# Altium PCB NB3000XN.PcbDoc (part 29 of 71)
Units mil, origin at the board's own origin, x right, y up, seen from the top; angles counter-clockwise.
Board outline 9527.56 x 6929.77 mil, 6 copper layers (Top Layer, GND+SHIELD, MidLayer1, MidLayer2, P2 - 3V3+5V0, Bottom Layer), stack 62.375 mil thick; 832 components, 1027 nets, 4655 pads, 4981 vias.
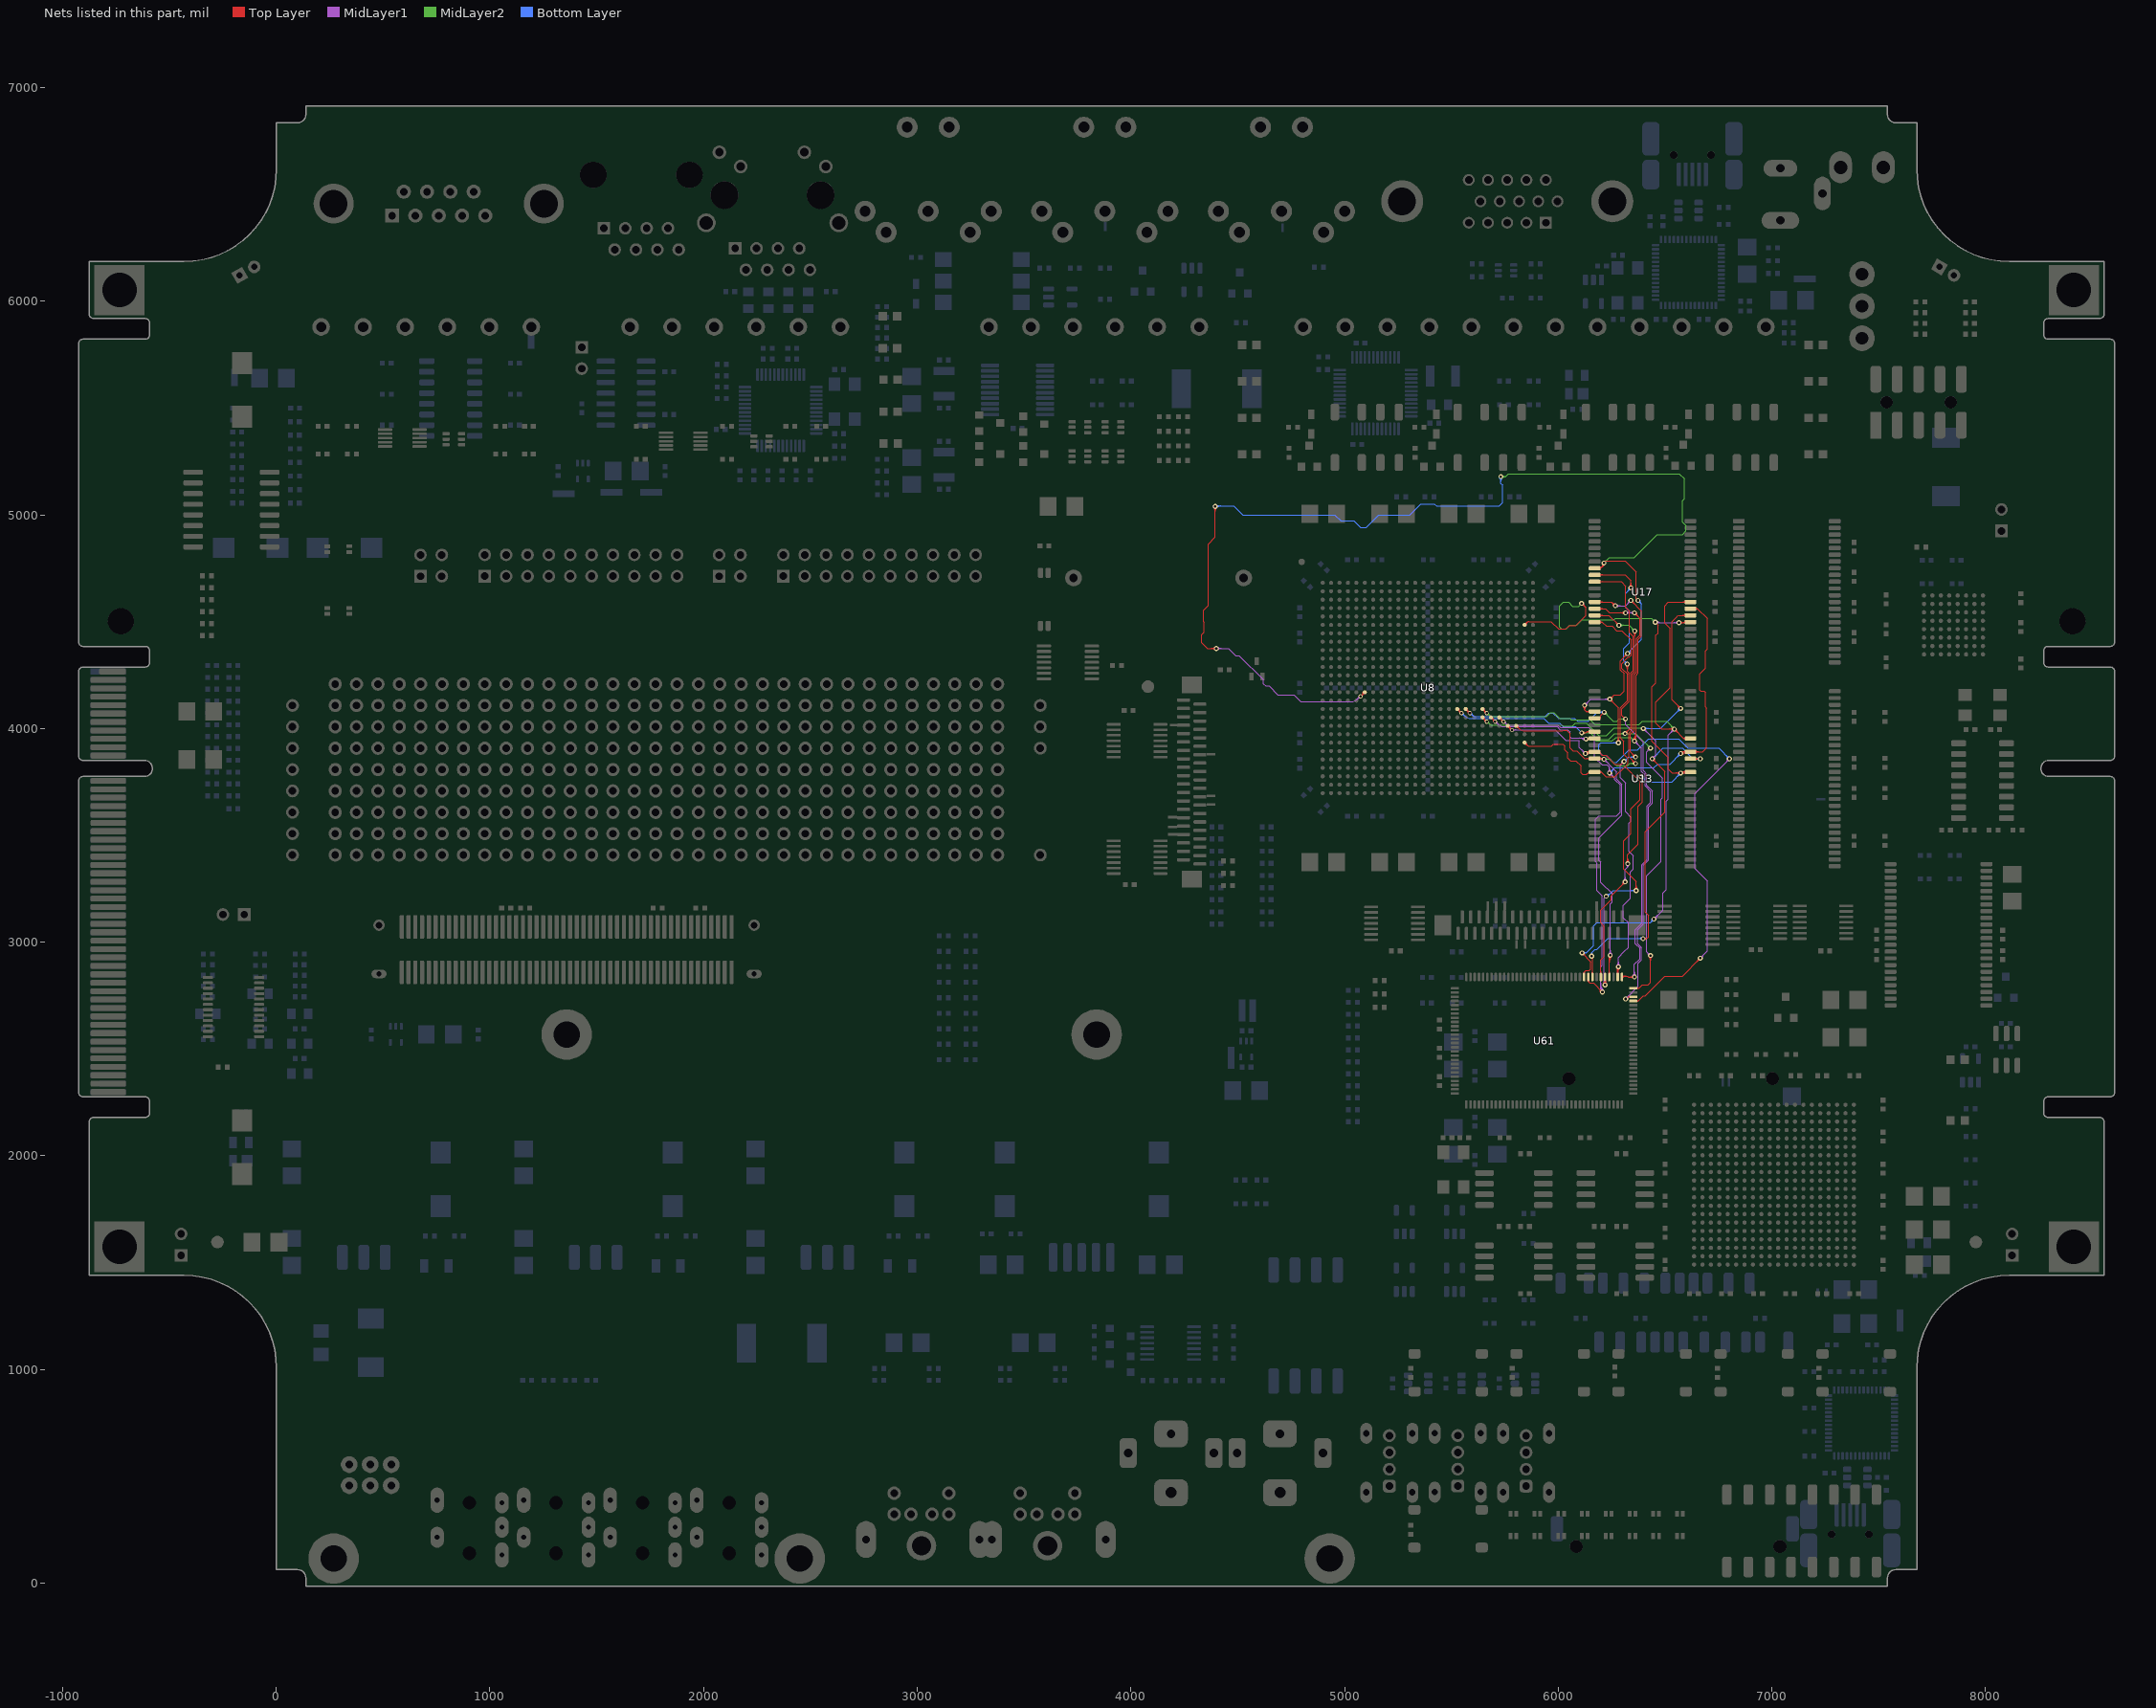
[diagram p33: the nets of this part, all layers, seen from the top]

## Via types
v1: diameter 23, hole 11.81, Top Layer to Bottom Layer, 3672 vias
v2: diameter 26, hole 11.81, Top Layer to Bottom Layer, 461 vias
v3: diameter 19, hole 11.81, Top Layer to Bottom Layer, tented both sides, 396 vias
v4: diameter 23.62, hole 11.81, Top Layer to Bottom Layer, 288 vias
v5: diameter 20, hole 11.81, Top Layer to Bottom Layer, 91 vias
v6: diameter 23, hole 11.81, Top Layer to Bottom Layer, tented both sides, 50 vias
v7: diameter 31, hole 11.81, Top Layer to Bottom Layer, 15 vias
v8: diameter 27.56, hole 11.81, Top Layer to Bottom Layer, tented both sides, 4 vias
v9: diameter 29, hole 11.81, Top Layer to Bottom Layer, 3 vias
v10: diameter 21, hole 11.81, Top Layer to Bottom Layer, 1 vias

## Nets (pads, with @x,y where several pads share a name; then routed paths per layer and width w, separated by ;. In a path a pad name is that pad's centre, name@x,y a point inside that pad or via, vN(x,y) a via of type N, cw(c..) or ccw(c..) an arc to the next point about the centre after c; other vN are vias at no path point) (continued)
DB_MEM.BUS_D17: U8.P6 U13.4 U17.8 U61.61 | length 9838.7
  Top Layer w4: v1@4388.28,5033.28 cw(c4372.06,5017.06) 4395,5017.06 cw(c4417.93,5017.06) v1@4401.72,5033.28 ; v1@4391.11,5036.11 cw(c4381.72,5026.72) 4395,5026.72 cw(c4408.28,5026.72) v1@4398.89,5036.11 ; v4@4393.06,4368.1 ccw(c4376.31,4351.35) 4376.31,4375.04 ccw(c4376.31,4398.73) v4@4393.06,4381.98 ; v1(4395,5040) 4395,4896.1 4362.02,4863.13 4362.02,4577.02 4340,4555 4340,4500.59 4343,4497.59 4343,4451.2 4332.02,4440.23 4332.02,4401.13 4358.11,4375.04 v4(4400,4375.04) ; v4@4395.89,4370.93 ccw(c4385.97,4361.01) 4385.97,4375.04 ccw(c4385.97,4389.07) v4@4395.89,4379.15 ; v3(5075.04,4150.63) U8.P6@5094.72,4170.31 ; U8.P6@5087.22,4170.31 cw(c5069.12,4170.31) 5081.92,4157.51 cw(c5094.72,4144.71) U8.P6@5094.72,4162.81 ; U8.P6@5087.38,4170.31 cw(c5069.66,4170.31) 5082.19,4157.78 cw(c5094.72,4145.25) U8.P6@5094.72,4162.97 ; v1@6117.62,4101.27 cw(c6107.92,4089.04) 6123.52,4089.04 ; v1(6123.52,4108.71) 6123.52,4089.04 ; v1@6129.43,4101.27 ccw(c6139.13,4089.04) 6123.52,4089.04 ; U13.4@6147.37,4074.3 ccw(c6133.72,4060.65) 6133.72,4079.96 ccw(c6133.72,4099.27) U13.4@6147.37,4085.62 ; U13.4@6170.59,4079.96 6132.6,4079.96 6123.52,4089.04 ; U17.8@6170.59,4750.24 6199.72,4750.24 ; U17.8@6187.19,4746.35 ccw(c6190.23,4758.62) 6199.17,4749.68 ; U17.8@6188.15,4750.24 ccw(c6192.22,4766.65) 6204.17,4754.69 ; U17.8@6189.11,4754.12 ccw(c6194.21,4774.67) 6209.18,4759.7 ; U17.8@6190.07,4758 ccw(c6196.2,4782.7) v1@6214.19,4764.71 ; U17.8@6195.63,4747.41 cw(c6199.72,4745.87) 6199.72,4750.24 ; U17.8@6195.63,4753.06 ccw(c6199.72,4754.6) 6199.72,4750.24 ; 6204.89,4755.4 ccw(c6196.85,4763.44) v1@6206.29,4769.76 ; 6208.33,4758.85 ccw(c6200.98,4766.2) v1@6209.62,4771.98 ; 6211.77,4762.29 ccw(c6205.1,4768.96) v1@6212.94,4774.21 ; v1@6241.52,4128.21 cw(c6241.52,4105.27) 6257.74,4121.49 cw(c6273.96,4137.71) 6251.02,4137.71 cw(c6273.96,4137.71) 6257.74,4153.93 cw(c6241.52,4170.14) v1@6241.52,4147.21 ; v1@6241.52,4132.21 cw(c6241.52,4118.93) 6250.91,4128.32 cw(c6260.3,4137.71) 6247.02,4137.71 cw(c6260.3,4137.71) 6250.91,4147.1 cw(c6241.52,4156.49) v1@6241.52,4143.21 ; v1@6275.14,3940.09 ccw(c6258.92,3956.31) 6281.86,3956.31 ccw(c6304.79,3956.31) v1@6288.57,3940.09 ; v1@6277.97,3937.26 ccw(c6268.58,3946.65) 6281.86,3946.65 ccw(c6295.14,3946.65) v1@6285.75,3937.26 ; v1(6281.86,3933.37) 6281.86,4097.37 v1(6241.52,4137.71) 6262.19,4158.37 6290.19,4158.37 6307.86,4176.04 6307.86,4257.37 6290.19,4275.04 6290.19,4316.71 v1(6324.86,4351.37) ; v1@6315.36,4351.37 cw(c6292.42,4351.37) 6308.64,4335.16 cw(c6324.86,4318.94) v1@6324.86,4341.87 ; v1@6319.36,4351.37 cw(c6306.08,4351.37) 6315.47,4341.99 cw(c6324.86,4332.6) v1@6324.86,4345.87 ; U61.61@6351.93,2725.05 6373.53,2725.05 ; U61.61@6368.23,2722.52 cw(c6373.53,2718.22) 6373.53,2725.05 ; U61.61@6368.23,2727.57 ccw(c6373.53,2731.87) 6373.53,2725.05 ; v1(6373.52,4600.04) 6365.19,4608.37 6365.19,4733.71 6313.52,4785.37 6224.52,4785.37 v1(6214.19,4775.04) v1@6214.19,4764.71 ; v1@6655.69,2925.04 cw(c6632.76,2925.04) 6648.97,2908.82 cw(c6665.19,2892.61) v1@6665.19,2915.54 ; v1@6659.69,2925.04 cw(c6646.41,2925.04) 6655.8,2915.65 cw(c6665.19,2906.26) v1@6665.19,2919.54 ; v1(6665.19,2925.04) 6581.86,2841.71 6498.52,2841.71 6406.86,2750.04 6398.52,2750.04 6373.53,2725.05 ; 5087.84,4163.43 cw(c5075.04,4176.24) 5075.04,4158.13 ccw(c5075.04,4176.24) 5087.84,4163.43 ; 5087.84,4163.43 ccw(c5100.65,4150.63) 5082.54,4150.63 cw(c5100.65,4150.63) 5087.84,4163.43 ; 6199.72,4750.24 v1@6214.19,4764.71
  MidLayer1 w4: v4(4400,4375.04) 4456.86,4375.04 4490.19,4341.71 4506.86,4341.71 4620.07,4228.5 4620.07,4209.4 4630.5,4198.97 4646.87,4198.97 4688.29,4157.54 4730,4157.54 4764.33,4157.54 4773.52,4148.35 4795.11,4126.77 4855.26,4126.77 4860,4126.77 4870,4126.77 4918.62,4126.77 4938.04,4126.77 5012.16,4126.77 ; v4@4404.11,4370.93 cw(c4414.03,4361.01) 4414.03,4375.04 cw(c4414.03,4389.07) v4@4404.11,4379.15 ; v4@4406.94,4368.1 cw(c4423.69,4351.35) 4423.69,4375.04 cw(c4423.69,4398.73) v4@4406.94,4381.98 ; 4998.23,4126.77 5012.16,4126.77 ; v3@5067.57,4151.28 cw(c5049.53,4152.86) 5061.17,4138.99 ; v3@5074.39,4143.16 ccw(c5072.81,4125.12) 5061.17,4138.99 ; v1(6123.52,4108.71) 6152.52,4137.71 v1(6241.52,4137.71) ; v1@6123.52,4114.21 ccw(c6123.52,4127.49) 6132.91,4118.1 ccw(c6142.3,4108.71) v1@6129.02,4108.71 ; v1@6123.52,4118.21 ccw(c6123.52,4141.14) 6139.74,4124.93 ccw(c6155.96,4108.71) v1@6133.02,4108.71 ; v1@6234.81,4130.99 ccw(c6218.59,4114.77) 6218.59,4137.71 ccw(c6218.59,4160.64) v1@6234.81,4144.43 ; v1@6237.64,4133.82 ccw(c6228.25,4124.43) 6228.25,4137.71 ccw(c6228.25,4150.99) v1@6237.64,4141.6 ; v1(6665.19,2925.04) 6698.52,2958.37 6698.52,3286.35 6640.19,3344.69 6640.19,3696.71 v1(6801.86,3858.37) ; v1@6665.19,2930.54 ccw(c6665.19,2943.82) 6674.58,2934.43 ccw(c6683.97,2925.04) v1@6670.69,2925.04 ; v1@6665.19,2934.54 ccw(c6665.19,2957.48) 6681.41,2941.26 ccw(c6697.63,2925.04) v1@6674.69,2925.04 ; v1@6792.36,3858.37 cw(c6769.42,3858.37) 6785.64,3842.16 cw(c6801.86,3825.94) v1@6801.86,3848.87 ; v1@6796.36,3858.37 cw(c6783.08,3858.37) 6792.47,3848.99 cw(c6801.86,3839.6) v1@6801.86,3852.87 ; 5012.16,4126.77 5031.66,4126.77 ccw(c5031.66,4168.5) 5061.17,4138.99
  MidLayer2 w4: v1(5731.86,5179.04) 5753.21,5179.04 ; v1@5735.94,5175.36 cw(c5744.22,5167.9) 5744.22,5179.04 cw(c5744.22,5190.18) v1@5735.94,5182.72 ; v1@5738.91,5172.68 cw(c5753.21,5159.8) 5753.21,5179.04 ; v1@5738.91,5185.4 ccw(c5753.21,5198.28) 5753.21,5179.04 ; v1(6214.19,4775.04) 6239.19,4800.04 6356.21,4800.04 6464.54,4908.37 6581.86,4908.37 6598.52,4925.04 6598.52,4950.04 6581.86,4966.71 6581.86,5066.71 6590.19,5075.04 6590.19,5169.08 6567.56,5191.71 5765.88,5191.71 5753.21,5179.04 ; v1@6214.19,4780.54 ccw(c6214.19,4793.82) 6223.58,4784.43 ccw(c6232.97,4775.04) v1@6219.69,4775.04 ; v1@6214.19,4784.54 ccw(c6214.19,4807.48) 6230.41,4791.26 ccw(c6246.63,4775.04) v1@6223.69,4775.04
  Bottom Layer w4: v1(4395,5040) 4385.62,5040 4385.62,5041.71 4481.86,5041.71 4523.52,5000.04 4954.51,5000.04 4954.77,4999.77 ; v1@4398.89,5036.11 cw(c4412.4,5022.6) 4412.4,5041.71 ; v1@4401.72,5033.28 cw(c4422.06,5012.94) 4422.06,5041.71 ; v1@4401.72,5046.72 ccw(c4413.81,5058.81) 4413.81,5041.71 ; 4955,5000 4982.46,4972.54 5044.28,4972.54 5075.94,4940.87 5101.02,4940.87 5160.15,5000 5305.48,5000 5330.52,5025.04 5356.86,5051.37 5420.33,5051.37 5430,5041.71 5723.52,5041.71 5740.19,5058.37 5740.19,5140 5731.86,5148.33 v1(5731.86,5179.04) ; v1@5725.14,5172.32 cw(c5708.92,5156.11) 5731.86,5156.11 cw(c5754.79,5156.11) v1@5738.57,5172.32 ; v1@5727.97,5175.15 cw(c5718.58,5165.76) 5731.86,5165.76 cw(c5745.14,5165.76) v1@5735.75,5175.15 ; v1@6275.14,3926.66 ccw(c6258.92,3910.44) 6258.92,3933.37 ccw(c6258.92,3956.31) v1@6275.14,3940.09 ; v1@6277.97,3929.49 ccw(c6268.58,3920.1) 6268.58,3933.37 ccw(c6268.58,3946.65) v1@6277.97,3937.26 ; v1(6281.86,3933.37) 6198.52,3933.37 6190.19,3925.04 6190.19,3891.71 6206.86,3875.04 6223.52,3875.04 6257.02,3841.54 6272.44,3841.54 6330.27,3899.37 6371.48,3899.37 6422.82,3950.71 6564.52,3950.71 6606.86,3908.37 6751.86,3908.37 v1(6801.86,3858.37) ; v1(6324.86,4351.37) 6390.19,4416.71 6390.19,4583.37 v1(6373.52,4600.04) ; v1@6324.86,4356.87 ccw(c6324.86,4370.15) 6334.25,4360.76 ccw(c6343.64,4351.37) v1@6330.36,4351.37 ; v1@6324.86,4360.87 ccw(c6324.86,4383.81) 6341.07,4367.59 ccw(c6357.29,4351.37) v1@6334.36,4351.37 ; v1@6373.52,4590.54 cw(c6373.52,4567.61) 6389.74,4583.82 cw(c6405.96,4600.04) v1@6383.02,4600.04 ; v1@6373.52,4594.54 cw(c6373.52,4581.26) 6382.91,4590.65 cw(c6392.3,4600.04) v1@6379.02,4600.04 ; v1@6792.36,3858.37 ccw(c6769.42,3858.37) 6785.64,3874.59 ccw(c6801.86,3890.81) v1@6801.86,3867.87 ; v1@6796.36,3858.37 ccw(c6783.08,3858.37) 6792.47,3867.76 ccw(c6801.86,3877.15) v1@6801.86,3863.87
DB_MEM.BUS_D18: U8.T18 U13.5 U17.9 U61.62 | length 3809.3
  Top Layer w4: U8.T18@5567.17,4084.07 cw(c5567.17,4065.97) 5579.97,4078.77 cw(c5592.77,4091.57) U8.T18@5574.67,4091.57 ; U8.T18@5567.17,4084.23 cw(c5567.17,4066.51) 5579.7,4079.04 cw(c5592.23,4091.57) U8.T18@5574.51,4091.57 ; U8.T18@5567.17,4091.57 v3(5586.85,4071.89) ; U13.5@6170.59,4048.46 6198.15,4048.46 6200.15,4050.46 6200.15,4061.33 v1(6215.19,4076.37) ; U17.9@6170.59,4718.74 6313.16,4718.74 6340.19,4691.71 v1(6340.19,4658.37) ; U17.9@6193.81,4713.08 cw(c6207.46,4699.43) 6207.46,4718.74 cw(c6207.46,4738.05) U17.9@6193.81,4724.4 ; v1(6315,4045) 6298.19,4061.81 6298.19,4093.06 6331.86,4126.73 6331.86,4260 6323.52,4268.33 v1(6323.52,4301.71) ; v1(6315.52,2734.37) 6319.64,2734.37 6330,2744.73 ; v1@6316.81,4294.99 cw(c6300.59,4278.77) 6323.52,4278.77 cw(c6346.46,4278.77) v1@6330.24,4294.99 ; v1@6319.64,4297.82 cw(c6310.25,4288.43) 6323.52,4288.43 cw(c6336.8,4288.43) v1@6327.41,4297.82 ; v1@6333.47,4665.09 ccw(c6317.26,4681.31) 6340.19,4681.31 ccw(c6363.13,4681.31) v1@6346.91,4665.09 ; U61.62@6335.71,2742.12 ccw(c6330,2737.18) 6330,2744.73 ; U61.62@6335.71,2747.35 cw(c6330,2752.28) 6330,2744.73 ; v1@6336.3,4662.26 ccw(c6326.91,4671.65) 6340.19,4671.65 ccw(c6353.47,4671.65) v1@6344.08,4662.26 ; U61.62@6351.93,2744.73 6330,2744.73 ; 5574.05,4084.69 cw(c5561.24,4071.89) 5579.35,4071.89 ccw(c5561.24,4071.89) 5574.05,4084.69 ; 5574.05,4084.69 ccw(c5586.85,4097.5) 5586.85,4079.39 cw(c5586.85,4097.5) 5574.05,4084.69
  MidLayer1 w4: v1@6315.19,4044.81 6315.19,4018.04 6398.52,3934.71 6398.52,3803.04 6415.19,3786.37 6415.19,3734.04 6440.86,3708.37 6440.86,3651.37 6423.52,3634.04 6423.52,3384.37 6398.86,3359.71 6398.86,3085.06 6371.19,3057.39 6371.19,2994.04 6390.19,2975.04 6390.19,2916.71 6374.86,2901.37 6374.86,2793.71 v1(6315.52,2734.37) ; v1@6315.52,2739.87 ccw(c6315.52,2753.15) 6324.91,2743.76 ccw(c6334.3,2734.37) v1@6321.02,2734.37 ; v1@6315.52,2743.87 ccw(c6315.52,2766.81) 6331.74,2750.59 ccw(c6347.96,2734.37) v1@6325.02,2734.37
  MidLayer2 w4: v1@6215.19,4066.87 cw(c6215.19,4043.94) 6231.41,4060.16 cw(c6247.63,4076.37) v1@6224.69,4076.37 ; v1@6215.19,4070.87 cw(c6215.19,4057.6) 6224.58,4066.99 cw(c6233.97,4076.37) v1@6220.69,4076.37 ; v1(6215.19,4076.37) 6256.56,4035 6275,4035 6284.81,4044.81 v1@6315.19,4044.81
  Bottom Layer w4: v3@5587.5,4064.42 cw(c5589.08,4046.38) 5600.72,4060.25 cw(c5612.36,4074.12) v3@5594.32,4072.54 ; 5600.43,4060.5 ccw(c5610.36,4070.43) 5610.36,4056.38 5703.9,4056.38 5910,4056.38 5920,4056.38 5924.74,4056.38 5938.41,4056.38 5954.52,4072.5 5976.19,4072.5 5997.19,4051.5 5997.19,4051.37 5999.86,4048.71 6076.88,4048.71 6092.21,4033.37 6140.19,4033.37 6183.19,4076.37 v1(6215.19,4076.37) ; v1@6208.47,4069.66 ccw(c6192.26,4053.44) 6192.26,4076.37 ccw(c6192.26,4099.31) v1@6208.47,4083.09 ; v1@6211.3,4072.49 ccw(c6201.91,4063.1) 6201.91,4076.37 ccw(c6201.91,4089.65) v1@6211.3,4080.26 ; v1@6314.02,4301.71 ccw(c6291.09,4301.71) 6307.31,4317.93 ccw(c6323.52,4334.14) v1@6323.52,4311.21 ; v1@6318.02,4301.71 ccw(c6304.75,4301.71) 6314.14,4311.1 ccw(c6323.52,4320.49) v1@6323.52,4307.21 ; v1(6323.52,4301.71) 6306.86,4318.37 6306.86,4374.71 6332.86,4400.71 6332.86,4549.04 6315.19,4566.71 6315.19,4633.37 v1(6340.19,4658.37) ; v1@6330.69,4658.37 cw(c6307.76,4658.37) 6323.97,4642.16 cw(c6340.19,4625.94) v1@6340.19,4648.87 ; v1@6334.69,4658.37 cw(c6321.41,4658.37) 6330.8,4648.99 cw(c6340.19,4639.6) v1@6340.19,4652.87
DB_MEM.BUS_D19: U8.T17 U13.7 U17.10 U61.64 | length 3878.3
  Top Layer w4: U8.T17@5527.8,4084.07 cw(c5527.8,4065.97) 5540.6,4078.77 cw(c5553.4,4091.57) U8.T17@5535.3,4091.57 ; U8.T17@5527.8,4084.23 cw(c5527.8,4066.51) 5540.33,4079.04 cw(c5552.86,4091.57) U8.T17@5535.14,4091.57 ; U8.T17@5527.8,4091.57 v3(5547.48,4071.89) ; v1(6110,3980) 6129.53,3980 ; v1@6117.47,3974.14 cw(c6129.53,3964.68) 6129.53,3980 ; v1@6117.47,3985.86 ccw(c6129.53,3995.32) 6129.53,3980 ; U13.7@6147.1,3980.1 ccw(c6135,3969.15) 6135,3985.47 ; U13.7@6147.1,3990.84 cw(c6135,4001.79) 6135,3985.47 ; U13.7@6170.59,3985.47 6135,3985.47 ; U17.10@6170.59,4687.24 6294.66,4687.24 6315.19,4666.71 6315.19,4566.71 6332.86,4549.04 6332.86,4449.04 6350.52,4431.37 6350.52,4270.65 6339.86,4259.98 6339.86,4003.71 v1(6312.86,3976.71) ; U17.10@6193.81,4681.59 cw(c6207.46,4667.93) 6207.46,4687.24 cw(c6207.46,4706.56) U17.10@6193.81,4692.9 ; v1@6312.86,3982.21 ccw(c6312.86,3995.49) 6322.25,3986.1 ccw(c6331.64,3976.71) v1@6318.36,3976.71 ; v1@6312.86,3986.21 ccw(c6312.86,4009.14) 6329.07,3992.93 ccw(c6345.29,3976.71) v1@6322.36,3976.71 ; U61.64@6351.93,2784.1 6377.52,2784.1 6394.8,2801.37 6421.37,2801.37 6431.86,2811.86 v1(6431.86,2937.37) ; U61.64@6367.96,2781.27 cw(c6374.78,2774.44) 6374.78,2784.1 cw(c6374.78,2793.76) U61.64@6367.96,2786.93 ; v1@6425.14,2930.66 cw(c6408.92,2914.44) 6431.86,2914.44 cw(c6454.79,2914.44) v1@6438.57,2930.66 ; v1@6427.97,2933.49 cw(c6418.58,2924.1) 6431.86,2924.1 cw(c6445.14,2924.1) v1@6435.75,2933.49 ; 5534.68,4084.69 cw(c5521.87,4071.89) 5539.98,4071.89 ccw(c5521.87,4071.89) 5534.68,4084.69 ; 5534.68,4084.69 ccw(c5547.48,4097.5) 5547.48,4079.39 cw(c5547.48,4097.5) 5534.68,4084.69 ; 6129.53,3980 6135,3985.47
  MidLayer1 w4: v1@6422.36,2937.37 ccw(c6399.42,2937.37) 6415.64,2953.59 ccw(c6431.86,2969.81) v1@6431.86,2946.87 ; v1@6422.36,3908.37 cw(c6399.42,3908.37) 6415.64,3892.16 cw(c6431.86,3875.94) v1@6431.86,3898.87 ; v1@6426.36,2937.37 ccw(c6413.08,2937.37) 6422.47,2946.76 ccw(c6431.86,2956.15) v1@6431.86,2942.87 ; v1@6426.36,3908.37 cw(c6413.08,3908.37) 6422.47,3898.99 cw(c6431.86,3889.6) v1@6431.86,3902.87 ; v1(6431.86,2937.37) 6414.86,2954.37 6414.86,3311.36 6481.86,3378.36 6481.86,3669.69 6489.19,3677.02 6489.19,3767.71 6415.19,3841.71 6415.19,3891.71 v1(6431.86,3908.37)
  MidLayer2 w4: v1(6110,3980) 6150.56,3980 6180.52,3950.04 6237.19,3950.04 6263.86,3976.71 v1(6312.86,3976.71) 6363.52,3976.71 6385.4,3954.83 v1(6431.86,3908.37) ; v1@6113.89,3976.11 cw(c6123.28,3966.72) 6123.28,3980 cw(c6123.28,3993.28) v1@6113.89,3983.89 ; v1@6116.72,3973.28 cw(c6132.93,3957.06) 6132.93,3980 cw(c6132.93,4002.93) v1@6116.72,3986.72 ; v1@6306.14,3969.99 ccw(c6289.92,3953.77) 6289.92,3976.71 ccw(c6289.92,3999.64) v1@6306.14,3983.43 ; v1@6308.97,3972.82 ccw(c6299.58,3963.43) 6299.58,3976.71 ccw(c6299.58,3989.99) v1@6308.97,3980.6 ; v1@6316.75,3972.82 cw(c6326.14,3963.43) 6326.14,3976.71 cw(c6326.14,3989.99) v1@6316.75,3980.6 ; v1@6319.57,3969.99 cw(c6335.79,3953.77) 6335.79,3976.71 cw(c6335.79,3999.64) v1@6319.57,3983.43 ; v1@6422.36,3908.37 ccw(c6399.42,3908.37) 6415.64,3924.59 ccw(c6431.86,3940.81) v1@6431.86,3917.87 ; v1@6426.36,3908.37 ccw(c6413.08,3908.37) 6422.47,3917.76 ccw(c6431.86,3927.15) v1@6431.86,3913.87
  Bottom Layer w4: v3@5548.13,4064.42 cw(c5549.71,4046.38) 5561.35,4060.25 ; v3@5554.95,4072.54 ccw(c5572.99,4074.12) 5561.35,4060.25 ; v1(6110,3980) 6081.29,4008.71 6023.19,4008.71 6006.86,4025.04 5954.84,4025.04 5931.86,4048.03 5924.74,4048.03 5920,4048.03 5910,4048.03 5703.9,4048.03 5684.48,4048.03 5610.36,4048.03 5590.86,4048.03 cw(c5590.86,4089.76) 5561.35,4060.25
DB_MEM.BUS_D20: U8.U21 U13.8 U17.13 U61.65 | length 3875
  Top Layer w4: U8.U21@5685.28,4044.7 cw(c5685.28,4026.6) 5698.08,4039.4 cw(c5710.88,4052.2) U8.U21@5692.78,4052.2 ; U8.U21@5685.28,4044.86 cw(c5685.28,4027.14) 5697.81,4039.67 cw(c5710.34,4052.2) U8.U21@5692.62,4052.2 ; U8.U21@5685.28,4052.2 v3(5704.96,4032.52) ; v1@6130.36,3953.98 U13.8@6170.59,3953.98 ; v1@6131.43,3949.81 cw(c6141.49,3939.74) 6141.49,3953.98 ; v1@6134.25,3946.98 cw(c6151.15,3930.08) U13.8@6151.15,3953.98 ; v1@6137.08,3944.15 cw(c6160.8,3920.43) U13.8@6160.8,3953.98 ; v1@6137.08,3957.58 ccw(c6145.8,3966.3) U13.8@6145.8,3953.98 ; U13.8@6147.37,3948.32 ccw(c6133.72,3934.66) 6133.72,3953.98 ccw(c6133.72,3973.29) U13.8@6147.37,3959.63 ; U17.13@6170.59,4592.76 6249.81,4592.76 v1(6267.52,4575.04) ; U17.13@6193.81,4587.1 cw(c6207.46,4573.44) 6207.46,4592.76 cw(c6207.46,4612.07) U17.13@6193.81,4598.41 ; v1@6258.02,4575.04 ccw(c6235.09,4575.04) 6251.31,4591.26 ccw(c6267.52,4607.48) v1@6267.52,4584.54 ; v1@6262.02,4575.04 ccw(c6248.75,4575.04) 6258.14,4584.43 ccw(c6267.52,4593.82) v1@6267.52,4580.54 ; U61.65@6298.34,2837.34 cw(c6308.9,2826.79) 6308.9,2841.71 ; U61.65@6298.35,2841.71 6325,2841.71 6329.33,2837.37 v1(6356.86,2837.37) ; U61.65@6301.17,2834.51 cw(c6318.55,2817.13) 6318.55,2841.71 ; v1@6340.19,4590.54 cw(c6340.19,4567.61) 6356.41,4583.82 cw(c6372.63,4600.04) v1@6349.69,4600.04 ; v1@6340.19,4594.54 cw(c6340.19,4581.26) 6349.58,4590.65 cw(c6358.97,4600.04) v1@6345.69,4600.04 ; v1(6340.19,4600.04) 6390.19,4550.04 6390.19,4434.02 6374.52,4418.35 6374.52,4260.71 6363.86,4250.04 6363.86,3948.71 v1(6356.86,3941.71) ; v1@6350.14,2830.66 ccw(c6333.92,2814.44) 6333.92,2837.37 ccw(c6333.92,2860.31) v1@6350.14,2844.09 ; v1@6350.14,3948.43 ccw(c6317.02,3981.54) 6363.86,3981.54 ; v1@6352.97,2833.49 ccw(c6343.58,2824.1) 6343.58,2837.37 ccw(c6343.58,2850.65) v1@6352.97,2841.26 ; v1@6352.97,3945.6 ccw(c6326.68,3971.89) 6363.86,3971.89 ; v1@6355.8,3942.77 ccw(c6336.34,3962.23) 6363.86,3962.23 ; v1@6358.62,3939.94 ccw(c6345.99,3952.57) 6363.86,3952.57 ; 5692.16,4045.32 cw(c5679.35,4032.52) 5697.46,4032.52 ccw(c5679.35,4032.52) 5692.16,4045.32 ; 5692.16,4045.32 ccw(c5704.96,4058.13) 5704.96,4040.02 cw(c5704.96,4058.13) 5692.16,4045.32
  MidLayer1 w4: v3@5705.61,4025.05 cw(c5707.19,4007.01) 5718.83,4020.88 ; v3@5712.43,4033.17 ccw(c5730.47,4034.75) 5718.83,4020.88 ; 6097.45,3955 cw(c6097.45,3917.96) v1@6123.65,3944.15 ; 6107.11,3955 cw(c6107.11,3927.61) v1@6126.48,3946.98 ; 6116.77,3955 cw(c6116.77,3937.27) v1@6129.3,3949.81 ; 6117.41,3955 ccw(c6117.41,3963.83) v1@6123.65,3957.58 ; v1(6130.36,3950.87) 6126.23,3955 6060,3955 6055,3960 6055,3985 6045,3995 6008.69,3995 5995.03,4008.66 5920,4008.66 5910,4008.66 5861.38,4008.66 5841.96,4008.66 5767.84,4008.66 5748.34,4008.66 cw(c5748.34,4050.39) 5718.83,4020.88 ; v1(6267.52,4575.04) 6315.19,4575.04 v1(6340.19,4600.04) ; v1@6271.41,4571.15 cw(c6280.8,4561.76) 6280.8,4575.04 cw(c6280.8,4588.32) v1@6271.41,4578.93 ; v1@6274.24,4568.32 cw(c6290.46,4552.11) 6290.46,4575.04 cw(c6290.46,4597.98) v1@6274.24,4581.76 ; v1@6330.69,4600.04 cw(c6307.76,4600.04) 6323.97,4583.82 cw(c6340.19,4567.61) v1@6340.19,4590.54 ; v1@6334.69,4600.04 cw(c6321.41,4600.04) 6330.8,4590.65 cw(c6340.19,4581.26) v1@6340.19,4594.54 ; v1@6350.14,2844.09 ccw(c6333.92,2860.31) 6356.86,2860.31 ccw(c6379.79,2860.31) v1@6363.57,2844.09 ; v1@6352.97,2841.26 ccw(c6343.58,2850.65) 6356.86,2850.65 ccw(c6370.14,2850.65) v1@6360.75,2841.26 ; v1(6356.86,2837.37) 6356.86,2896.04 6381.86,2921.04 6381.86,2972.06 6361.52,2992.39 6361.52,3059.04 6390.86,3088.37 6390.86,3363.02 6415.52,3387.69 6415.52,3637.36 6432.86,3654.69 6432.86,3705.06 6406.86,3731.06 6406.86,3783.37 6390.19,3800.04 6390.19,3908.37 v1(6356.86,3941.71) ; v1@6356.86,3932.21 cw(c6356.86,3909.27) 6373.07,3925.49 cw(c6389.29,3941.71) v1@6366.36,3941.71 ; v1@6356.86,3936.21 cw(c6356.86,3922.93) 6366.25,3932.32 cw(c6375.64,3941.71) v1@6362.36,3941.71
  MidLayer2 w4: v1(6130.36,3950.87) 6168.38,3950.87 6177.54,3941.71 6252.52,3941.71 6269.86,3959.04 6339.52,3959.04 v1(6356.86,3941.71) ; v1@6134.25,3946.98 cw(c6143.64,3937.59) 6143.64,3950.87 cw(c6143.64,3964.15) v1@6134.25,3954.76 ; v1@6137.08,3944.15 cw(c6153.3,3927.93) 6153.3,3950.87 cw(c6153.3,3973.8) v1@6137.08,3957.58 ; v1@6347.36,3941.71 ccw(c6324.42,3941.71) 6340.64,3957.93 ccw(c6356.86,3974.14) v1@6356.86,3951.21 ; v1@6351.36,3941.71 ccw(c6338.08,3941.71) 6347.47,3951.1 ccw(c6356.86,3960.49) v1@6356.86,3947.21
DB_MEM.BUS_D21: U8.V23 U13.10 U17.14 U61.66 | length 3740.1
  Top Layer w4: U8.V23@5764.02,4005.33 cw(c5764.02,3987.23) 5776.82,4000.03 cw(c5789.62,4012.83) U8.V23@5771.52,4012.83 ; U8.V23@5764.02,4005.49 cw(c5764.02,3987.77) 5776.55,4000.3 cw(c5789.08,4012.83) U8.V23@5771.36,4012.83 ; U8.V23@5764.02,4012.83 v3(5783.7,3993.15) ; v1@6125.76,3885.14 cw(c6139.86,3871.04) 6139.86,3890.98 ; v1(6127.52,3883.37) v1@6135.13,3890.98 ; v1@6128.58,3882.31 cw(c6149.52,3861.38) U13.10@6149.52,3890.98 ; v1@6131.41,3879.49 cw(c6159.17,3851.73) U13.10@6159.17,3890.98 ; v1@6134.24,3876.66 cw(c6168.83,3842.07) U13.10@6168.83,3890.98 ; U13.10@6147.07,3885.65 ccw(c6135.13,3874.96) v1@6135.13,3890.98 ; U13.10@6147.07,3896.32 cw(c6135.13,3907) v1@6135.13,3890.98 ; U17.14@6170.59,4561.26 6220.64,4561.26 6240.19,4541.71 v1(6315.19,4541.71) ; U13.10@6188.15,3882.98 cw(c6188.15,3857) 6206.53,3875.37 ; U13.10@6188.15,3886.98 cw(c6188.15,3870.65) 6199.7,3882.2 ; U17.14@6193.81,4555.6 cw(c6207.46,4541.95) 6207.46,4561.26 cw(c6207.46,4580.57) U17.14@6193.81,4566.92 ; U13.10@6196.15,3890.98 ccw(c6208.79,3890.98) 6199.85,3882.05 ; v1@6275.14,2878.32 cw(c6266.64,2869.82) 6278.66,2869.82 ; U61.66@6275.83,2853.36 ccw(c6269,2860.19) 6278.66,2860.19 ccw(c6288.32,2860.19) U61.66@6281.49,2853.36 ; U61.66@6278.66,2837.34 v1@6278.66,2881.84 ; U61.66@6278.66,2854.39 cw(c6312.51,2854.39) v1@6288.57,2878.32 ; 6278.66,2864.04 cw(c6302.85,2864.04) v1@6285.75,2881.15 ; 6278.66,2873.7 cw(c6293.2,2873.7) v1@6282.92,2883.98 ; v1(6308.19,3846.04) 6295.52,3833.37 6265.19,3833.37 6223.52,3875.04 6206.86,3875.04 6190.91,3890.98 U13.10@6170.59,3890.98 v1@6135.13,3890.98 ; v1@6308.47,4534.99 ccw(c6292.26,4518.77) 6292.26,4541.71 ccw(c6292.26,4564.64) v1@6308.47,4548.43 ; v1@6311.3,4537.82 ccw(c6301.91,4528.43) 6301.91,4541.71 ccw(c6301.91,4554.99) v1@6311.3,4545.6 ; v1@6352.69,3866.71 ccw(c6329.76,3866.71) 6345.97,3882.93 ccw(c6362.19,3899.14) v1@6362.19,3876.21 ; v1@6356.69,3866.71 ccw(c6343.41,3866.71) 6352.8,3876.1 ccw(c6362.19,3885.49) v1@6362.19,3872.21 ; v1@6356.86,4532.21 cw(c6356.86,4509.27) 6373.07,4525.49 cw(c6389.29,4541.71) v1@6366.36,4541.71 ; v1@6356.86,4536.21 cw(c6356.86,4522.93) 6366.25,4532.32 cw(c6375.64,4541.71) v1@6362.36,4541.71 ; v1(6356.86,4541.71) 6381.86,4516.71 6381.86,4437 6366.52,4421.67 6366.52,4264.02 6355.86,4253.35 6355.86,3990.04 6338.86,3973.04 6338.86,3890.04 v1(6362.19,3866.71) ; 5770.9,4005.95 cw(c5758.09,3993.15) 5776.2,3993.15 ccw(c5758.09,3993.15) 5770.9,4005.95 ; 5770.9,4005.95 ccw(c5783.7,4018.76) 5783.7,4000.65 cw(c5783.7,4018.76) 5770.9,4005.95
  MidLayer1 w4: v3(5783.7,3993.15) 5861.38,3993.15 5910,3993.15 5920,3993.15 5986.23,3993.15 6035,3944.37 6096.86,3944.37 6099.52,3941.71 6099.52,3911.37 v1(6127.52,3883.37) ; v3@5788.89,3987.96 cw(c5801.43,3975.42) 5801.43,3993.15 cw(c5801.43,4010.88) v3@5788.89,3998.34 ; v3@5789,3987.85 cw(c5801.81,3975.04) 5801.81,3993.15 cw(c5801.81,4011.26) v3@5789,3998.45 ; v1@6118.02,3883.37 ccw(c6095.09,3883.37) 6111.31,3899.59 ccw(c6127.52,3915.81) v1@6127.52,3892.87 ; v1@6122.02,3883.37 ccw(c6108.75,3883.37) 6118.14,3892.76 ccw(c6127.52,3902.15) v1@6127.52,3888.87 ; v1@6275.14,2891.76 ccw(c6258.92,2907.98) 6281.86,2907.98 ccw(c6304.79,2907.98) v1@6288.57,2891.76 ; v1@6277.97,2888.93 ccw(c6268.58,2898.32) 6281.86,2898.32 ccw(c6295.14,2898.32) v1@6285.75,2888.93 ; v1(6281.86,2885.04) 6281.86,2928.39 6310,2956.54 6329.52,2976.04 6329.52,3090.69 6305.19,3115.02 6305.19,3171.73 6338.86,3205.39 6338.86,3329.37 6351.19,3341.71 6351.19,3405.71 6331.86,3425.04 6331.86,3558.37 6340.19,3566.71 6340.19,3585 6314.86,3610.33 6314.86,3745.33 6290.19,3770 6290.19,3828.04 v1(6308.19,3846.04) ; v1@6298.69,3846.04 cw(c6275.76,3846.04) 6291.97,3829.82 cw(c6308.19,3813.61) v1@6308.19,3836.54 ; v1@6302.69,3846.04 cw(c6289.41,3846.04) 6298.8,3836.65 cw(c6308.19,3827.26) v1@6308.19,3840.54 ; v1(6315.19,4541.71) v1(6356.86,4541.71) ; v1@6319.08,4537.82 cw(c6328.47,4528.43) 6328.47,4541.71 cw(c6328.47,4554.99) v1@6319.08,4545.6 ; v1@6321.91,4534.99 cw(c6338.13,4518.77) 6338.13,4541.71 cw(c6338.13,4564.64) v1@6321.91,4548.43 ; v1@6350.14,4534.99 ccw(c6333.92,4518.77) 6333.92,4541.71 ccw(c6333.92,4564.64) v1@6350.14,4548.43 ; v1@6352.97,4537.82 ccw(c6343.58,4528.43) 6343.58,4541.71 ccw(c6343.58,4554.99) v1@6352.97,4545.6
  Bottom Layer w4: v1(6308.19,3846.04) 6328.86,3866.71 v1(6362.19,3866.71) ; v1@6308.19,3851.54 ccw(c6308.19,3864.82) 6317.58,3855.43 ccw(c6326.97,3846.04) v1@6313.69,3846.04 ; v1@6308.19,3855.54 ccw(c6308.19,3878.48) 6324.41,3862.26 ccw(c6340.63,3846.04) v1@6317.69,3846.04 ; v1@6355.47,3859.99 ccw(c6339.26,3843.77) 6339.26,3866.71 ccw(c6339.26,3889.64) v1@6355.47,3873.43 ; v1@6358.3,3862.82 ccw(c6348.91,3853.43) 6348.91,3866.71 ccw(c6348.91,3879.99) v1@6358.3,3870.6
DB_MEM.BUS_D22: U8.V24 U13.11 U17.15 U61.68 | length 3430.7
  Top Layer w4: U8.V24@5803.39,4005.49 cw(c5803.39,3987.77) 5815.92,4000.3 ; U8.V24@5810.73,4012.83 ccw(c5828.45,4012.83) 5815.92,4000.3 ; U13.11@6147.37,3853.83 ccw(c6133.72,3840.18) 6133.72,3859.49 ccw(c6133.72,3878.8) U13.11@6147.37,3865.15 ; U17.15@6170.59,4529.76 6238.14,4529.76 v1(6284.52,4483.37) ; U13.11@6183.74,3859.49 cw(c6183.74,3825.92) v1@6207.47,3849.66 ; U13.11@6193.4,3859.49 cw(c6193.4,3835.58) v1@6210.3,3852.49 ; U17.15@6193.81,4524.11 cw(c6207.46,4510.45) 6207.46,4529.76 cw(c6207.46,4549.08) U17.15@6193.81,4535.42 ; U13.11@6194.73,3854.94 cw(c6203.41,3848.93) v1@6203.41,3859.49 ; U13.11@6194.73,3864.04 ccw(c6203.41,3870.04) v1@6203.41,3859.49 ; 6198.77,3859.49 ccw(c6198.77,3871.79) v1@6207.47,3863.09 ; 6203.05,3859.49 cw(c6203.05,3845.24) v1@6213.13,3855.31 ; v1(6214.19,3856.37) 6206.52,3856.37 v1@6203.41,3859.49 ; U61.68@6236.46,2853.36 ccw(c6229.63,2860.19) 6239.29,2860.19 ccw(c6248.95,2860.19) U61.68@6242.12,2853.36 ; v1@6236.81,2931.99 cw(c6230.81,2925.99) 6239.29,2925.99 ; U61.68@6239.29,2837.34 6239.29,2934.47 v1(6243.52,2938.71) ; 6239.29,2905.55 cw(c6276.68,2905.55) v1@6250.24,2931.99 ; 6239.29,2915.21 cw(c6267.02,2915.21) v1@6247.41,2934.82 ; 6239.29,2924.86 cw(c6257.37,2924.86) v1@6244.58,2937.65 ; v1@6275.02,4483.37 ccw(c6252.09,4483.37) 6268.31,4499.59 ccw(c6284.52,4515.81) v1@6284.52,4492.87 ; v1@6279.02,4483.37 ccw(c6265.75,4483.37) 6275.14,4492.76 ccw(c6284.52,4502.15) v1@6284.52,4488.87 ; v1@6351.81,4449.99 cw(c6335.59,4433.77) 6358.52,4433.77 cw(c6381.46,4433.77) v1@6365.24,4449.99 ; v1@6352.69,3836.37 ccw(c6329.76,3836.37) 6345.97,3852.59 ccw(c6362.19,3868.81) v1@6362.19,3845.87 ; v1@6354.64,4452.82 cw(c6345.25,4443.43) 6358.52,4443.43 cw(c6371.8,4443.43) v1@6362.41,4452.82 ; v1@6356.69,3836.37 ccw(c6343.41,3836.37) 6352.8,3845.76 ccw(c6362.19,3855.15) v1@6362.19,3841.87 ; v1(6358.52,4456.71) 6358.52,4267.34 6347.86,4256.67 6347.86,3995.37 6330.86,3978.37 6330.86,3867.71 v1(6362.19,3836.37) ; 5815.92,4000.3 ccw(c5843.27,4027.65) 5843.27,3988.97 5910,3988.97 5920,3988.97 5924.74,3988.97 6020.26,3988.97 6024,3992.71 6039.19,3992.71 6055.52,3976.37 6056.02,3975.87 6056.02,3909.46 6070.11,3895.37 6086.52,3895.37 6122.19,3859.71 6122.19,3859.49 v1@6203.41,3859.49
  MidLayer1 w4: v1@6214.19,3846.87 cw(c6214.19,3823.94) 6230.41,3840.16 cw(c6246.63,3856.37) v1@6223.69,3856.37 ; v1@6214.19,3850.87 cw(c6214.19,3837.6) 6223.58,3846.99 cw(c6232.97,3856.37) v1@6219.69,3856.37 ; v1(6214.19,3856.37) 6255.13,3815.44 6273.52,3797.06 6273.52,3764.04 6298.52,3739.04 6298.52,3595.71 6190.19,3487.37 6190.19,3383.37 6198.52,3375.04 6198.52,3305 6198.52,3283.37 6198.52,3280.69 6251.94,3227.28 6251.94,3186.79 6243.52,3178.37 v1(6243.52,2938.71) ; v1@6236.81,2945.43 ccw(c6220.59,2961.64) 6243.52,2961.64 ccw(c6266.46,2961.64) v1@6250.24,2945.43 ; v1@6239.64,2942.6 ccw(c6230.25,2951.99) 6243.52,2951.99 ccw(c6256.8,2951.99) v1@6247.41,2942.6
  MidLayer2 w4: v1(6214.19,3856.37) 6242.19,3856.37 6273.52,3825.04 6325,3825.04 6336.33,3836.37 v1(6362.19,3836.37) ; v1@6218.08,3852.49 cw(c6227.47,3843.1) 6227.47,3856.37 cw(c6227.47,3869.65) v1@6218.08,3860.26 ; v1@6220.91,3849.66 cw(c6237.13,3833.44) 6237.13,3856.37 cw(c6237.13,3879.31) v1@6220.91,3863.09 ; v1(6284.52,4483.37) 6331.86,4483.37 v1(6358.52,4456.71) ; v1@6288.41,4479.49 cw(c6297.8,4470.1) 6297.8,4483.37 cw(c6297.8,4496.65) v1@6288.41,4487.26 ; v1@6291.24,4476.66 cw(c6307.46,4460.44) 6307.46,4483.37 cw(c6307.46,4506.31) v1@6291.24,4490.09 ; v1@6349.02,4456.71 ccw(c6326.09,4456.71) 6342.31,4472.93 ccw(c6358.52,4489.14) v1@6358.52,4466.21 ; v1@6353.02,4456.71 ccw(c6339.75,4456.71) 6349.14,4466.1 ccw(c6358.52,4475.49) v1@6358.52,4462.21 ; v1@6355.47,3829.66 ccw(c6339.26,3813.44) 6339.26,3836.37 ccw(c6339.26,3859.31) v1@6355.47,3843.09 ; v1@6358.3,3832.49 ccw(c6348.91,3823.1) 6348.91,3836.37 ccw(c6348.91,3849.65) v1@6358.3,3840.26
DB_MEM.BUS_D23: U8.Y25 U13.13 U17.16 U61.69 | length 3222.3
  Top Layer w4: 6134.47,3786.47 cw(c6149.58,3771.36) U13.13@6152.49,3792.53 ; 6140.17,3792.17 cw(c6150.96,3781.38) U13.13@6153.03,3796.5 ; U13.13@6156.86,3796.5 U13.13@6170.59,3796.5 ; U17.16@6170.59,4498.27 6206.15,4498.27 ; U17.16@6194.09,4492.91 cw(c6206.15,4482.02) 6206.15,4498.27 ; U17.16@6194.09,4503.63 ccw(c6206.15,4514.52) 6206.15,4498.27 ; U13.13@6195.06,3792.47 cw(c6202.07,3788.39) 6202.07,3796.5 ; U13.13@6195.06,3800.52 ccw(c6202.07,3804.6) 6202.07,3796.5 ; v1@6212.47,2806.76 ccw(c6195.25,2823.98) U61.69@6219.6,2823.98 ; v1@6215.19,2804.04 v1(6219.19,2800.04) 6219.6,2800.46 U61.69@6219.6,2837.34 ; v1@6215.3,2803.93 ccw(c6204.91,2814.32) 6219.6,2814.32 ; U61.69@6216.78,2821.32 cw(c6209.95,2814.49) 6219.6,2814.49 cw(c6229.26,2814.49) U61.69@6222.43,2821.32 ; 6219.6,2812.32 ccw(c6231.47,2812.32) v1@6223.08,2803.93 ; U61.69@6219.6,2821.97 ccw(c6241.12,2821.97) v1@6225.91,2806.76 ; v1@6358.47,3248.43 ccw(c6342.26,3264.64) 6365.19,3264.64 ccw(c6388.13,3264.64) v1@6371.91,3248.43 ; v1@6361.3,3245.6 ccw(c6351.91,3254.99) 6365.19,3254.99 ccw(c6378.47,3254.99) v1@6369.08,3245.6 ; v1(6365.19,3241.71) 6365.19,3283.37 6306.86,3341.71 6306.86,3475.04 6340.19,3508.37 6340.19,3624.04 6382.86,3666.71 6382.86,3752.04 6312.52,3822.37 ; 5855.29,3921.56 ccw(c5862.47,3928.74) 5862.47,3918.59 ; 5855.29,3921.56 ccw(c5862.47,3928.74) 5862.47,3918.59 ; 5855.29,3921.56 cw(c5867.83,3934.09) 5850.1,3934.09 ccw(c5867.83,3934.09) 5855.29,3921.56 ; 5855.29,3921.56 ccw(c5842.76,3909.03) 5842.76,3926.75 cw(c5842.76,3909.03) 5855.29,3921.56 ; 5862.47,3918.59 5910,3918.59 5920,3918.59 5969.58,3918.59 5978.15,3927.15 6021.75,3927.15 6029.52,3919.37 6031.19,3917.71 6032.02,3916.87 6032.02,3899.52 6045.5,3886.04 6045.5,3861.65 6057.94,3849.21 6065,3849.21 6072.44,3849.21 6082.69,3849.21 6106.86,3825.04 6106.86,3793.37 6115.19,3785.04 6133.04,3785.04 6144.5,3796.5 U13.13@6170.59,3796.5 ; U13.13@6170.59,3796.5 6202.07,3796.5 ; 6202.07,3796.5 6224.52,3774.04 6264.19,3774.04 6312.52,3822.37 ; 6206.15,4498.27 6225.21,4479.21 6252.69,4479.21 6273.52,4458.37 6298.52,4458.37 6342.52,4414.37 6342.52,4344.04 6331.86,4333.37 6327.86,4333.37 6298.52,4304.04 6298.52,4280.71 6323.52,4255.71 6323.52,4129.71 6290.19,4096.37 6290.19,3956.37 6306.86,3939.71 6306.86,3880.04 6326.52,3860.37 6326.52,3836.37 6312.52,3822.37
  MidLayer1 w4: v1@6212.47,2806.76 ccw(c6205.91,2813.32) 6215.19,2813.32 ccw(c6232.47,2813.32) v1@6220.25,2801.1 ; 6215.19,2822.98 ccw(c6242.13,2822.98) v1@6223.08,2803.93 ; 6215.19,2832.63 ccw(c6251.78,2832.63) v1@6225.91,2806.76 ; v1(6219.19,2800.04) 6215.19,2804.04 6215.19,3205.04 v1(6225.19,3215.04)
  Bottom Layer w4: v1(6225.19,3215.04) 6230.19,3215.04 6256.86,3241.71 v1(6365.19,3241.71) ; v1@6225.19,3216.54 ccw(c6225.19,3232.23) 6236.29,3221.14 ; v1@6225.19,3220.54 ccw(c6225.19,3245.89) 6243.11,3227.97 ; v1@6225.19,3224.54 ccw(c6225.19,3259.55) 6249.94,3234.79 ; v1@6234.69,3215.04 cw(c6245.55,3215.04) 6237.87,3222.72 ; v1@6358.47,3234.99 ccw(c6342.26,3218.77) 6342.26,3241.71 ccw(c6342.26,3264.64) v1@6358.47,3248.43 ; v1@6361.3,3237.82 ccw(c6351.91,3228.43) 6351.91,3241.71 ccw(c6351.91,3254.99) v1@6361.3,3245.6
DB_MEM.BUS_D24: U8.F25 U13.42 U17.29 U61.70 | length 4207.8
  Top Layer w4: v1@6109.52,4576.54 cw(c6109.52,4553.61) 6125.74,4569.82 cw(c6141.96,4586.04) v1@6119.02,4586.04 ; v1@6109.52,4580.54 cw(c6109.52,4567.26) 6118.91,4576.65 cw(c6128.3,4586.04) v1@6115.02,4586.04 ; v1(6109.52,4586.04) 6128.86,4566.71 6128.86,4530.04 6081.86,4483.04 6053.04,4483.04 6036.71,4466.71 6001.01,4466.71 5966.93,4500.78 5924.74,4500.78 5920,4500.78 5910,4500.78 5862.47,4500.78 ; U61.70@6197.09,2853.36 ccw(c6193.63,2856.82) 6198.52,2856.82 ; U61.70@6198.52,2841.71 6198.52,2916.71 6215.19,2933.37 6215.19,3074.04 6198.52,3090.71 6198.52,3150.04 6248.52,3200.04 6248.52,3217.71 v1(6313.19,3282.37) ; 6198.52,2863.56 ccw(c6212.95,2863.56) U61.70@6202.75,2853.36 ; v1@6303.69,3282.37 cw(c6280.76,3282.37) 6296.97,3266.16 cw(c6313.19,3249.94) v1@6313.19,3272.87 ; v1@6307.69,3282.37 cw(c6294.41,3282.37) 6303.8,3272.99 cw(c6313.19,3263.6) v1@6313.19,3276.87 ; v1@6318.81,3374.43 ccw(c6302.59,3390.64) 6325.52,3390.64 ccw(c6348.46,3390.64) v1@6332.24,3374.43 ; v1@6321.64,3371.6 ccw(c6312.25,3380.99) 6325.52,3380.99 ccw(c6338.8,3380.99) v1@6329.41,3371.6 ; v1(6325.52,3367.71) 6325.52,3410.37 6373.52,3458.37 6373.52,3636.04 6394.19,3656.71 6394.19,3768.37 v1(6387.52,3775.04) ; v1(6454.52,4498.04) 6467.52,4485.04 6467.52,4446.69 6457.52,4436.69 6457.52,4377.04 6457.52,4355 6457.52,4212.81 6439.86,4195.14 6439.86,3940.14 6514.86,3865.14 6514.86,3810.14 6533.29,3791.71 v1(6573.52,3791.71) ; v1@6566.81,3784.99 ccw(c6550.59,3768.77) 6550.59,3791.71 ccw(c6550.59,3814.64) v1@6566.81,3798.43 ; v1@6569.41,4491.49 cw(c6578.8,4482.1) 6578.8,4495.37 cw(c6578.8,4508.65) v1@6569.41,4499.26 ; v1@6569.64,3787.82 ccw(c6560.25,3778.43) 6560.25,3791.71 ccw(c6560.25,3804.99) v1@6569.64,3795.6 ; v1@6570.19,4500.04 v1(6565.52,4495.37) 6602.11,4495.37 U17.29@6605,4498.27 ; v1@6572.24,4488.66 cw(c6588.46,4472.44) 6588.46,4495.37 cw(c6588.46,4518.31) v1@6572.24,4502.09 ; v1@6574.58,3790.65 cw(c6588.7,3776.53) 6588.7,3796.5 ; v1@6575.55,4495.37 ccw(c6575.55,4524.57) U17.29@6596.19,4503.92 ; v1@6577.41,3787.82 cw(c6598.36,3766.87) U13.42@6598.36,3796.5 ; v1@6580.24,3784.99 cw(c6608.02,3757.21) U13.42@6608.02,3796.5 ; v1@6580.24,3798.43 ccw(c6584.9,3803.08) 6584.9,3796.5 ; 6585.21,4495.37 ccw(c6585.21,4514.91) U17.29@6599.02,4501.1 ; 6589.52,4495.37 cw(c6589.52,4485.94) U17.29@6596.19,4492.61 ; U13.42@6596.19,3790.84 ccw(c6582.54,3777.18) 6582.54,3796.5 ccw(c6582.54,3815.81) U13.42@6596.19,3802.15 ; U13.42@6619.41,3796.5 v1@6578.19,3796.5 ; 5855.29,4497.81 cw(c5862.47,4490.63) 5862.47,4500.78 ; 5855.29,4497.81 cw(c5862.47,4490.63) 5862.47,4500.78 ; 5855.29,4497.81 ccw(c5867.83,4485.28) 5850.1,4485.28 cw(c5867.83,4485.28) 5855.29,4497.81 ; 5855.29,4497.81 cw(c5842.76,4510.34) 5842.76,4492.62 ccw(c5842.76,4510.34) 5855.29,4497.81 ; v1(6573.52,3791.71) 6578.19,3796.37 v1@6578.19,3796.5 ; v1(6573.52,3791.71) 6573.52,3791.83 v1@6578.19,3796.5
  MidLayer1 w4: v1@6306.47,3289.09 ccw(c6290.26,3305.31) 6313.19,3305.31 ccw(c6336.13,3305.31) v1@6319.91,3289.09 ; v1@6309.3,3286.26 ccw(c6299.91,3295.65) 6313.19,3295.65 ccw(c6326.47,3295.65) v1@6317.08,3286.26 ; v1(6313.19,3282.37) 6313.19,3339.37 6325.52,3351.71 ; v1@6320.98,3359.37 cw(c6316.8,3351.71) 6325.52,3351.71 ; v1(6325.52,3367.71) 6325.52,3351.71 ; v1@6330.07,3359.37 ccw(c6334.25,3351.71) 6325.52,3351.71 ; v1(6454.52,4498.04) 6457.19,4495.37 v1(6565.52,4495.37) ; v1@6458.41,4501.93 ccw(c6474.24,4517.76) 6474.24,4495.37 ; v1@6461.24,4491.32 cw(c6471.02,4481.54) 6471.02,4495.37 ; v1@6461.24,4504.76 ccw(c6483.9,4527.41) 6483.9,4495.37 ; v1@6558.81,4488.66 ccw(c6542.59,4472.44) 6542.59,4495.37 ccw(c6542.59,4518.31) v1@6558.81,4502.09 ; v1@6561.64,4491.49 ccw(c6552.25,4482.1) 6552.25,4495.37 ccw(c6552.25,4508.65) v1@6561.64,4499.26
  MidLayer2 w4: v1(6109.52,4586.04) 6095.86,4572.37 6067.86,4572.37 6048.52,4591.71 6023.52,4591.71 6006.86,4575.04 6006.86,4475.04 6015.19,4466.71 6037.52,4466.71 6054.19,4483.37 6087.52,4483.37 6112.52,4508.37 6259.19,4508.37 6267.52,4516.71 6435.86,4516.71 v1(6454.52,4498.04) ; v1@6445.02,4498.04 ccw(c6422.09,4498.04) 6438.31,4514.26 ccw(c6454.52,4530.48) v1@6454.52,4507.54 ; v1@6449.02,4498.04 ccw(c6435.75,4498.04) 6445.14,4507.43 ccw(c6454.52,4516.82) v1@6454.52,4503.54
  Bottom Layer w4: v1@6387.52,3765.54 cw(c6387.52,3736.17) 6408.29,3756.94 ; v1@6387.52,3769.54 cw(c6387.52,3749.83) 6401.46,3763.77 ; v1(6387.52,3775.04) 6390.19,3775.04 6415.19,3750.04 6531.86,3750.04 v1(6573.52,3791.71) ; v1@6397.02,3775.04 ccw(c6413.52,3775.04) 6401.86,3763.37 ; v1@6564.02,3791.71 cw(c6541.09,3791.71) 6557.31,3775.49 cw(c6573.52,3759.27) v1@6573.52,3782.21 ; v1@6568.02,3791.71 cw(c6554.75,3791.71) 6564.14,3782.32 cw(c6573.52,3772.93) v1@6573.52,3786.21
DB_MEM.BUS_D25: U8.U20 U13.44 U17.30 U61.72 | length 4076.1
  Top Layer w4: U8.U20@5645.91,4044.7 cw(c5645.91,4026.6) 5658.71,4039.4 cw(c5671.51,4052.2) U8.U20@5653.41,4052.2 ; U8.U20@5645.91,4044.86 cw(c5645.91,4027.14) 5658.44,4039.67 cw(c5670.97,4052.2) U8.U20@5653.25,4052.2 ; U8.U20@5645.91,4052.2 v3(5665.59,4032.52) ; v1(6156.86,2934.71) 6161.19,2930.37 U61.72@6161.19,2850.04 ; U61.72@6157.72,2853.36 ccw(c6149.35,2861.73) 6161.19,2861.73 ; 6161.19,2858.64 ccw(c6168.66,2858.64) U61.72@6163.38,2853.36 ; v1(6397.19,3016.71) 6415.19,3016.71 ; v1@6405.03,3011.35 cw(c6415.19,3004.41) 6415.19,3016.71 ; v1@6405.03,3022.07 ccw(c6415.19,3029.01) 6415.19,3016.71 ; v1@6440.19,3848.87 cw(c6440.19,3825.94) 6456.41,3842.16 cw(c6472.63,3858.37) v1@6449.69,3858.37 ; v1@6440.19,3852.87 cw(c6440.19,3839.6) 6449.58,3848.99 cw(c6458.97,3858.37) v1@6445.69,3858.37 ; v1(6440.19,3858.37) 6498.52,3800.04 6498.52,3608.04 6406.86,3516.37 6406.86,3141.71 6423.52,3125.04 6423.52,3025.04 6415.19,3016.71 ; v1@6564.02,4094.37 ccw(c6541.09,4094.37) 6557.31,4110.59 ccw(c6573.52,4126.81) v1@6573.52,4103.87 ; v1@6568.02,4094.37 ccw(c6554.75,4094.37) 6564.13,4103.76 ccw(c6573.52,4113.15) v1@6573.52,4099.87 ; v1(6573.52,4094.37) 6531.86,4136.04 6531.86,4500.04 6557.42,4525.6 6558.52,4526.71 6561.58,4529.76 U17.30@6619.41,4529.76 ; U17.30@6596.19,4524.11 ccw(c6582.54,4510.45) 6582.54,4529.76 ccw(c6582.54,4549.08) U17.30@6596.19,4535.42 ; U13.44@6619.41,3859.49 6649.19,3859.49 ; U13.44@6644.3,3856.29 cw(c6649.19,3854.15) 6649.19,3859.49 ; U13.44@6644.3,3862.69 ccw(c6649.19,3864.82) 6649.19,3859.49 ; v1(6665.19,3858.37) 6650.3,3858.37 6649.19,3859.49 ; 5652.79,4045.32 cw(c5639.98,4032.52) 5658.09,4032.52 ccw(c5639.98,4032.52) 5652.79,4045.32 ; 5652.79,4045.32 ccw(c5665.59,4058.13) 5665.59,4040.02 cw(c5665.59,4058.13) 5652.79,4045.32
  MidLayer1 w4: v1@6398.52,3990.54 cw(c6398.52,3967.61) 6414.74,3983.82 cw(c6430.96,4000.04) v1@6408.02,4000.04 ; v1@6398.52,3994.54 cw(c6398.52,3981.26) 6407.91,3990.65 cw(c6417.3,4000.04) v1@6404.02,4000.04 ; v1(6398.52,4000.04) 6456.86,3941.71 6456.86,3875.04 v1(6440.19,3858.37) ; v1@6440.19,3863.87 ccw(c6440.19,3877.15) 6449.58,3867.76 ccw(c6458.97,3858.37) v1@6445.69,3858.37 ; v1@6440.19,3867.87 ccw(c6440.19,3890.81) 6456.41,3874.59 ccw(c6472.63,3858.37) v1@6449.69,3858.37
  MidLayer2 w4: v3@5666.24,4025.05 cw(c5667.82,4007.01) 5679.46,4020.88 cw(c5691.1,4034.75) v3@5673.06,4033.17 ; 5679.17,4021.13 ccw(c5689.1,4031.06) 5689.1,4017.01 5782.64,4017.01 5910,4017.01 5920,4017.01 6018.27,4017.01 6024.24,4011.04 6066.52,4011.04 6080.52,4025.04 6131.86,4025.04 6190.19,3966.71 6225.19,3966.71 6260.86,4002.37 6396.19,4002.37 v1(6398.52,4000.04)
  Bottom Layer w4: v1@6152.16,2942.97 ccw(c6147.57,2951.04) 6156.86,2951.04 ; v1(6156.86,2934.71) 6156.86,2951.04 ; v1@6161.55,2942.97 cw(c6166.15,2951.04) 6156.86,2951.04 ; v1@6390.47,3009.99 ccw(c6374.26,2993.77) 6374.26,3016.71 ccw(c6374.26,3039.64) v1@6390.47,3023.43 ; v1@6393.3,3012.82 ccw(c6383.91,3003.43) 6383.91,3016.71 ccw(c6383.91,3029.99) v1@6393.3,3020.6 ; v1(6397.19,3016.71) 6231.86,3016.71 6181.86,2966.71 6172.52,2966.71 6156.86,2951.04 ; v1(6398.52,4000.04) 6479.19,4000.04 v1(6573.52,4094.37) ; v1@6402.41,3996.15 cw(c6411.8,3986.76) 6411.8,4000.04 cw(c6411.8,4013.32) v1@6402.41,4003.93 ; v1@6405.24,3993.32 cw(c6421.46,3977.11) 6421.46,4000.04 cw(c6421.46,4022.98) v1@6405.24,4006.76 ; v1(6440.19,3858.37) 6490.19,3908.37 6581.86,3908.37 6631.86,3858.37 v1(6665.19,3858.37) ; v1@6440.19,3863.87 ccw(c6440.19,3877.15) 6449.58,3867.76 ccw(c6458.97,3858.37) v1@6445.69,3858.37 ; v1@6440.19,3867.87 ccw(c6440.19,3890.81) 6456.41,3874.59 ccw(c6472.63,3858.37) v1@6449.69,3858.37 ; v1@6564.02,4094.37 cw(c6541.09,4094.37) 6557.31,4078.16 cw(c6573.52,4061.94) v1@6573.52,4084.87 ; v1@6568.02,4094.37 cw(c6554.75,4094.37) 6564.14,4084.99 cw(c6573.52,4075.6) v1@6573.52,4088.87 ; v1@6658.47,3851.66 ccw(c6642.26,3835.44) 6642.26,3858.37 ccw(c6642.26,3881.31) v1@6658.47,3865.09 ; v1@6661.3,3854.49 ccw(c6651.91,3845.1) 6651.91,3858.37 ccw(c6651.91,3871.65) v1@6661.3,3862.26
DB_MEM.BUS_D26: U8.U22 U13.45 U17.31 U61.73 | length 3979.1
  Top Layer w4: U8.U22@5724.65,4044.7 cw(c5724.65,4026.6) 5737.45,4039.4 cw(c5750.25,4052.2) U8.U22@5732.15,4052.2 ; U8.U22@5724.65,4044.86 cw(c5724.65,4027.14) 5737.18,4039.67 cw(c5749.71,4052.2) U8.U22@5731.99,4052.2 ; U8.U22@5724.65,4052.2 v3(5744.33,4032.52) ; U61.73@6138.19,2821.17 cw(c6134.14,2816.68) 6140.19,2816.68 cw(c6144.49,2816.68) U61.73@6142.61,2820.55 ; U61.73@6140.19,2837.34 6140.19,2816.71 6148.52,2808.37 6165.19,2808.37 v1(6206.86,2766.71) ; U61.73@6140.86,2824.14 ccw(c6145.86,2820.11) 6141.32,2815.58 ; U61.73@6143.98,2821.63 ccw(c6149.34,2817.3) 6144.47,2812.43 ; v1@6197.36,2766.71 ccw(c6174.42,2766.71) 6190.64,2782.93 ccw(c6206.86,2799.14) v1@6206.86,2776.21 ; v1@6201.36,2766.71 ccw(c6188.08,2766.71) 6197.47,2776.1 ccw(c6206.86,2785.49) v1@6206.86,2772.21 ; v1@6571.76,3885.14 cw(c6585.86,3871.04) 6585.86,3890.98 ; v1(6573.52,3883.37) 6581.13,3890.98 U13.45@6619.41,3890.98 6675.98,3890.98 6695,3910 6695,4095.23 6688.52,4101.71 6688.52,4169.71 6681.86,4176.37 6666.52,4176.37 6662.52,4180.37 6662.52,4255.71 6690.19,4283.37 6690.19,4364 6698.52,4372.33 6698.52,4514.98 6652.24,4561.26 ; v1@6574.58,3882.31 cw(c6595.52,3861.38) U13.45@6595.52,3890.98 ; v1@6577.41,3879.49 cw(c6605.17,3851.73) U13.45@6605.17,3890.98 ; v1@6580.24,3876.66 cw(c6614.83,3842.07) U13.45@6614.83,3890.98 ; U13.45@6596.19,3885.33 ccw(c6582.54,3871.67) 6582.54,3890.98 ccw(c6582.54,3910.3) U13.45@6596.19,3896.64 ; U17.31@6619.41,4561.26 6652.24,4561.26 ; U13.45@6642.63,3885.33 cw(c6656.28,3871.67) 6656.28,3890.98 cw(c6656.28,3910.3) U13.45@6642.63,3896.64 ; U17.31@6643.54,4556.7 cw(c6652.24,4550.68) 6652.24,4561.26 ; U17.31@6643.54,4565.82 ccw(c6652.24,4571.84) 6652.24,4561.26 ; 5731.53,4045.32 cw(c5718.72,4032.52) 5736.83,4032.52 ccw(c5718.72,4032.52) 5731.53,4045.32 ; 5731.53,4045.32 ccw(c5744.33,4058.13) 5744.33,4040.02 cw(c5744.33,4058.13) 5731.53,4045.32
  MidLayer1 w4: v3@5744.98,4025.05 cw(c5746.56,4007.01) 5758.2,4020.88 ; 5757.91,4021.13 ccw(c5767.84,4031.06) 5767.84,4017.01 5861.38,4017.01 5910,4017.01 5920,4017.01 5997.99,4017.01 6010.5,4004.5 6063.11,4004.5 6064.48,4005.87 6142.81,4005.87 6170,3978.69 6170,3865 6205,3830 6229.25,3830 6240.19,3819.06 v1(6240.19,3791.71) 6265,3766.9 6265,3761.25 6290.19,3736.06 6290.19,3608.37 6273.52,3591.71 6190.19,3591.71 6173.52,3575.04 6173.52,3377.41 6182.19,3368.75 6182.19,3241.71 6206.86,3217.04 6206.86,2891.71 6198.52,2883.37 6198.52,2775.04 v1(6206.86,2766.71) ; 6198.52,2780.79 ccw(c6220.94,2780.79) v1@6205.09,2764.94 ; 6198.52,2790.45 ccw(c6230.6,2790.45) v1@6207.92,2767.77 ; 6198.52,2800.1 ccw(c6240.25,2800.1) v1@6210.75,2770.6 ; 6198.52,2809.76 ccw(c6249.91,2809.76) v1@6213.57,2773.43 ; v1@6233.47,3798.43 ccw(c6217.26,3814.64) 6240.19,3814.64 ccw(c6263.13,3814.64) v1@6246.91,3798.43 ; v1@6236.3,3795.6 ccw(c6226.91,3804.99) 6240.19,3804.99 ccw(c6253.47,3804.99) v1@6244.08,3795.6 ; v1@6240.19,3782.21 cw(c6240.19,3759.27) 6256.41,3775.49 cw(c6272.63,3791.71) v1@6249.69,3791.71 ; v1@6240.19,3786.21 cw(c6240.19,3772.93) 6249.58,3782.32 cw(c6258.97,3791.71) v1@6245.69,3791.71 ; 5758.2,4020.88 cw(c5769.84,4034.75) 5751.8,4033.17 ccw(c5769.84,4034.75) 5758.2,4020.88
  Bottom Layer w4: v1(6240.19,3791.71) 6265.19,3816.71 6448.52,3816.71 6465.19,3833.37 6523.52,3833.37 v1(6573.52,3883.37) ; v1@6240.19,3797.21 ccw(c6240.19,3810.49) 6249.58,3801.1 ccw(c6258.97,3791.71) v1@6245.69,3791.71 ; v1@6240.19,3801.21 ccw(c6240.19,3824.14) 6256.41,3807.93 ccw(c6272.63,3791.71) v1@6249.69,3791.71 ; v1@6564.02,3883.37 cw(c6541.09,3883.37) 6557.31,3867.16 cw(c6573.52,3850.94) v1@6573.52,3873.87 ; v1@6568.02,3883.37 cw(c6554.75,3883.37) 6564.14,3873.99 cw(c6573.52,3864.6) v1@6573.52,3877.87
DB_MEM.BUS_D27: U8.T20 U13.47 U17.32 U61.74 | length 4048.2
  Top Layer w4: U8.T20@5645.91,4084.07 cw(c5645.91,4065.97) 5658.71,4078.77 cw(c5671.51,4091.57) U8.T20@5653.41,4091.57 ; U8.T20@5645.91,4084.23 cw(c5645.91,4066.51) 5658.44,4079.04 cw(c5670.97,4091.57) U8.T20@5653.25,4091.57 ; U8.T20@5645.91,4091.57 v3(5665.59,4071.89) ; v1@6111.86,2940.54 cw(c6111.86,2917.61) 6128.07,2933.82 cw(c6144.29,2950.04) v1@6121.36,2950.04 ; v1@6111.86,2944.54 cw(c6111.86,2931.26) 6121.25,2940.65 cw(c6130.64,2950.04) v1@6117.36,2950.04 ; v1(6111.86,2950.04) 6152.86,2909.04 6152.86,2875.04 6144.52,2866.71 6129.18,2866.71 6121.18,2858.71 ; U61.74@6118.72,2853.69 ccw(c6114.82,2858.71) 6121.18,2858.71 ; U61.74@6121.18,2837.34 6121.18,2858.71 ; U61.74@6123.64,2853.69 cw(c6127.54,2858.71) 6121.18,2858.71 ; v1@6536.81,3990.99 ccw(c6520.59,3974.77) 6520.59,3997.71 ccw(c6520.59,4020.64) v1@6536.81,4004.43 ; v1@6539.64,3993.82 ccw(c6530.25,3984.43) 6530.25,3997.71 ccw(c6530.25,4010.99) v1@6539.64,4001.6 ; v1@6543.52,3988.21 cw(c6543.52,3965.27) 6559.74,3981.49 cw(c6575.96,3997.71) v1@6553.02,3997.71 ; v1@6543.52,3992.21 cw(c6543.52,3978.93) 6552.91,3988.32 cw(c6562.3,3997.71) v1@6549.02,3997.71 ; 6580.01,4591.71 ccw(c6580.01,4614.6) U17.32@6596.19,4598.41 ; 6585.07,4591.71 cw(c6585.07,4575.97) U17.32@6596.19,4587.1 ; 6589.66,4591.71 ccw(c6589.66,4604.94) U17.32@6599.02,4595.58 ; U13.47@6595.11,3949.67 ccw(c6587.26,3944.66) 6587.26,3953.98 ; U13.47@6595.11,3958.28 cw(c6587.26,3963.29) 6587.26,3953.98 ; U13.47@6619.41,3953.98 6587.26,3953.98 ; U17.32@6619.41,4592.76 6601.84,4592.76 6601.84,4591.71 6515.19,4591.71 6498.52,4575.04 6498.52,4493.35 6523.52,4468.35 6523.52,4191.71 6456.86,4125.04 6456.86,4025.04 6484.19,3997.71 v1(6543.52,3997.71) 6587.26,3953.98 ; 5652.79,4084.69 cw(c5639.98,4071.89) 5658.09,4071.89 ccw(c5639.98,4071.89) 5652.79,4084.69 ; 5652.79,4084.69 ccw(c5665.59,4097.5) 5665.59,4079.39 cw(c5665.59,4097.5) 5652.79,4084.69
  MidLayer1 w4: v1(6448.52,3108.37) 6490.19,3150.04 6490.19,3230.04 6506.86,3246.71 6506.86,3660.75 6515.19,3669.08 6515.19,3969.37 v1(6543.52,3997.71) ; v1@6448.52,3113.87 ccw(c6448.52,3127.15) 6457.91,3117.76 ccw(c6467.3,3108.37) v1@6454.02,3108.37 ; v1@6448.52,3117.87 ccw(c6448.52,3140.81) 6464.74,3124.59 ccw(c6480.96,3108.37) v1@6458.02,3108.37 ; v1@6534.02,3997.71 cw(c6511.09,3997.71) 6527.31,3981.49 cw(c6543.52,3965.27) v1@6543.52,3988.21 ; v1@6538.02,3997.71 cw(c6524.75,3997.71) 6534.13,3988.32 cw(c6543.52,3978.93) v1@6543.52,3992.21
  MidLayer2 w4: v3@5666.24,4064.42 cw(c5667.82,4046.38) 5679.46,4060.25 cw(c5691.1,4074.12) v3@5673.06,4072.54 ; 5679.17,4060.5 ccw(c5689.1,4070.43) 5689.1,4056.38 5782.64,4056.38 5910,4056.38 5920,4056.38 5945.38,4056.38 5964,4075 5980,4075 6007.5,4047.5 6055.06,4047.5 6060.86,4041.71 6149.52,4041.71 6172.86,4018.37 6379.19,4018.37 6394.19,4033.37 6507.86,4033.37 v1(6543.52,3997.71) ; v1@6534.02,3997.71 ccw(c6511.09,3997.71) 6527.31,4013.93 ccw(c6543.52,4030.14) v1@6543.52,4007.21 ; v1@6538.02,3997.71 ccw(c6524.75,3997.71) 6534.14,4007.1 ccw(c6543.52,4016.49) v1@6543.52,4003.21
  Bottom Layer w4: v1(6111.86,2950.04) 6131.86,2950.04 ; v1@6116.12,2946.57 cw(c6123.44,2940.6) 6123.44,2950.04 cw(c6123.44,2959.48) v1@6116.12,2953.52 ; v1@6119.22,2944.04 cw(c6131.86,2933.74) 6131.86,2950.04 ; v1@6119.22,2956.04 ccw(c6131.86,2966.34) 6131.86,2950.04 ; v1@6439.02,3108.37 cw(c6416.09,3108.37) 6432.31,3092.16 cw(c6448.52,3075.94) v1@6448.52,3098.87 ; v1@6443.02,3108.37 cw(c6429.75,3108.37) 6439.14,3098.99 cw(c6448.52,3089.6) v1@6448.52,3102.87 ; v1(6448.52,3108.37) 6432.19,3092.04 6180.29,3092.04 6165.19,3076.94 6165.19,2983.37 6131.86,2950.04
